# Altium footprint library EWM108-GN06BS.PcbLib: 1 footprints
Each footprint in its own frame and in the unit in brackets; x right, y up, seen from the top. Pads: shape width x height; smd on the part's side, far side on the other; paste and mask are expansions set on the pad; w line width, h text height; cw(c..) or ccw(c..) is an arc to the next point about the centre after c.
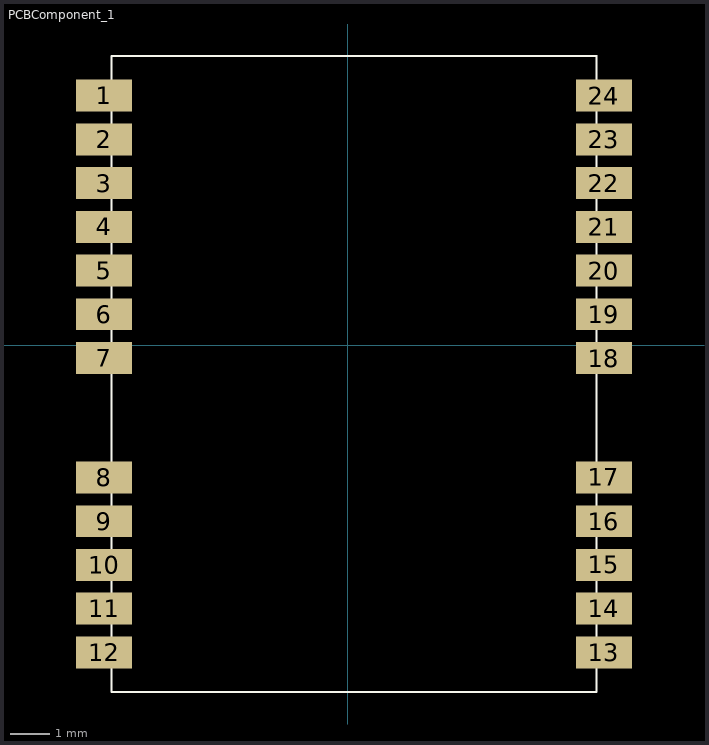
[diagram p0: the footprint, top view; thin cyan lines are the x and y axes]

## PCBComponent_1 [mm]
pads (24):
  rect 1.397x0.8 smd paste+0 mask+0: 1(-6.131,6.277) 2(-6.131,5.177) 3(-6.131,4.077) 4(-6.131,2.977) 5(-6.131,1.877) 6(-6.131,0.777) 7(-6.131,-0.323) 8(-6.131,-3.323) 9(-6.131,-4.423) 10(-6.131,-5.523) 11(-6.131,-6.623) 12(-6.131,-7.723) 13(6.439,-7.723) 14(6.439,-6.623) 15(6.439,-5.523) 16(6.439,-4.423) 17(6.439,-3.323) 18(6.439,-0.323) 19(6.439,0.777) 20(6.439,1.877) 21(6.439,2.977) 22(6.439,4.077) 23(6.439,5.177) 24(6.439,6.278)
Top Overlay:
  lines w0.05: 6.254,7.277 6.254,-8.723 -5.946,-8.723 -5.946,7.277 6.254,7.277 ; 6.254,7.277 6.254,7.277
